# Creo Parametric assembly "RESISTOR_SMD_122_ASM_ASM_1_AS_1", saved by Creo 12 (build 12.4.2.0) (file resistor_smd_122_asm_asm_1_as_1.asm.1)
Units: Custom; MM, KILOGRAM, SECS

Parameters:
  PTC_WM_ITERATION = "0"
  PTC_WM_VERSION = "-.0"
  PTC_WM_LIFECYCLE_STATE = "In Work"
  PTC_WM_LIFECYCLE = "MO_CADDocument"
  PTC_WM_CREATED_BY = "Maximilian Roepper (Z0017RMS: MO)"
  PTC_WM_CREATED_ON = "18-Sep-26 11:36:42 AM"
  PTC_WM_MODIFIED_BY = "Maximilian Roepper (Z0017RMS: MO)"
  PTC_WM_MODIFIED_ON = "18-Sep-26 11:36:46 AM"
  PDMLINKNUMBER = "PDM000071455188"
  PTC_WM_NUMBER = "PDM000071455188"

Other parameters: WEIGHT, WEIGHT_FACTOR, WEIGHT_ADD, MC_ERRORS, SUPPLIER

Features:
  1. coordinate system
  2. imported feature
  3. component "VALOR_PREDETERMINADO_2_PRT_1__1"

Other named items: DRW_VIEW_ORG, ROUGH-GROB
